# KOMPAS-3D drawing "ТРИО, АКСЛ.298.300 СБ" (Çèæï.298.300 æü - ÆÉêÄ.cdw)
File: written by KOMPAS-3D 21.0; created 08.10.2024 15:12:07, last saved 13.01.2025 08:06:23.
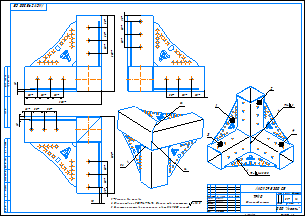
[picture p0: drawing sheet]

Sheet 1: A2, landscape

Document properties: Полное имя файла: ТРИО сборка.a3d; Автор: Алексей Бочаров; Масса: 5.166365

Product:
- Part/product: ТРИО  | designation АКСЛ.298.300 СБ
    Масса: 5.166365
    source file: АКСЛ.298.300 - ТРИО.spw, ТРИО спецификация.spw
  - Component [assembly]: Перемычка  | designation АКСЛ.298.201  | qty 3  | pos. 1  | Масса: 0.308618; source file: ..\Перемычка.stp
  - Component [detail]: Профиль L = 200 мм  | designation АКСЛ.298.301  | pos. 2  | Масса: 1.210897; Форматы листов документа: A2; source file: АКСЛ.298.301 - Профиль L = 200 мм.cdw, Профиль L = 200 мм.m3d
  - Component [detail]: Профиль L = 300 мм  | designation АКСЛ.298.302-01  | pos. 4  | Масса: 1.514806; source file: АКСЛ.298.302-01 - Профиль L = 300 мм.cdw, Профиль L = 300 мм (2).m3d
  - Component [detail]: Профиль L = 300 мм  | designation АКСЛ.298.302  | pos. 3  | Масса: 1.514806; Форматы листов документа: A2; source file: АКСЛ.298.302 - Профиль L = 300 мм.cdw, Профиль L = 300 мм (1).m3d

Title block, sheet 1: Наименование: ТРИО / Сборочный чертеж; designation: АКСЛ.298.300 СБ; Масса: 5,17; Количество листов документа: 1; organisation: ООО "Аксель"; Форматы листов документа: A2; stored path: C:\Users\Алексей Бочаров\Desktop\Соединения бруса\ТРИО\ТРИО Сборочный чертеж.cdw; Разработал: Бочаров; Проверил: Захаров; Утвердил: Гелетей

Referenced files in C:\Users\79253\YandexDisk\Соединения бруса\Соединения бруса\: Перемычка.stp
Referenced files in C:\Users\79253\YandexDisk\Соединения бруса\Соединения бруса\ТРИО\: Профиль L = 200 мм.m3d, АКСЛ.298.301 - Профиль L = 200 мм.cdw, Профиль L = 300 мм (2).m3d, АКСЛ.298.302-01 - Профиль L = 300 мм.cdw, Профиль L = 300 мм (1).m3d, АКСЛ.298.302 - Профиль L = 300 мм.cdw, ТРИО сборка.a3d
Referenced files in C:\Users\Алексей Бочаров\Desktop\Соединения бруса\ТРИО\: ТРИО сборка.a3d
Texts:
  АКСЛ.298.201
  Перемычка
  АКСЛ.298.301
  Профиль L = 200 мм
  АКСЛ.298.302 - 01
  АКСЛ.298.302 - 01
  Профиль L = 300 мм
  АКСЛ.298.302-01
  АКСЛ.298.302
  АКСЛ.298.300
  АКСЛ.298.302 Профиль L = 300 мм
  АКСЛ.298.302-01 Профиль L = 300 мм
  АКСЛ.298.301 Профиль L = 200 мм
  АКСЛ.298.201 Перемычка
  АКСЛ.298.300 СБ ТРИО
Dimensions and other numbers on the sheet: 3; 1; 1:2; 5,17; 01; 3D Узел_3; 3D Узел_3 3D Узел_3; 3D Узел_2; 3D Узел_2 3D Узел_2; 0; 0 0

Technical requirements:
  *Размеры для справок.
  Сварные швы по ГОСТ 14771-76. Сварные швы зачистить  Ra 12,5.
  Покрытие порошковое полимерное, цвет RAL 9005 черный.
